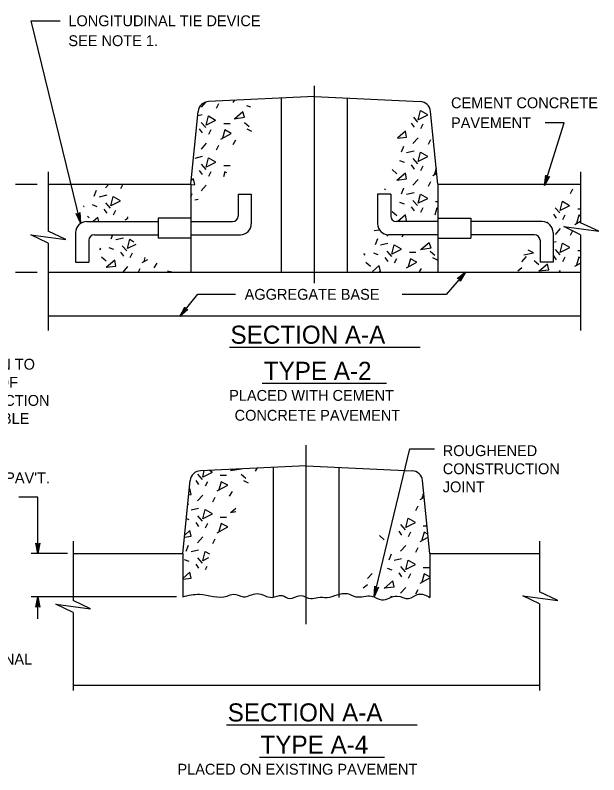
# Model space of a CAD drawing. Extents: x -49.1 to -41.9, y 44.5 to 54.6.
# Drawn here: x -45.264 to -42.042, y 50.267 to 54.464 of the extents above; entities that cross this region are included whole.
import ezdxf

# ---------------------------------------------------------------- set-up
doc = ezdxf.new("R2010")
doc.units = 0
for name, color, linetype in [('DETL-DIMS', 7, 'Continuous'), ('DETL-LINE', 7, 'Continuous'), ('DETL-NOTE', 7, 'Continuous'), ('DETL-PATT', 7, 'Continuous'), ('DETL-TITL', 7, 'Continuous')]:
    doc.layers.add(name, color=color, linetype=linetype)

msp = doc.modelspace()

# ---------------------------------------------------------------- linework, layer by layer
at = {"layer": 'DETL-DIMS'}
for p, q in [((-44.9035, 53.3158), (-45.1755, 54.4329)), ((-45.1755, 54.4329), (-45.0161, 54.4329)), ((-43.6122, 52.984), (-43.6122, 54.0742)), ((-42.3422, 53.5223), (-42.2343, 53.8696)), ((-42.2343, 53.8696), (-42.339, 53.8696)), ((-45.2621, 53.5295), (-45.1424, 53.5295)), ((-45.2621, 53.0446), (-45.1424, 53.0446)), ((-42.7789, 53.0446), (-42.8844, 52.9214)), ((-44.3546, 52.7995), (-44.2561, 52.9215)), ((-44.2561, 52.9215), (-44.0479, 52.9215)), ((-42.8844, 52.9214), (-43.1284, 52.9214)), ((-43.6569, 51.0992), (-43.6569, 52.088)), ((-43.2818, 51.2508), (-43.0853, 52.0677)), ((-43.0853, 52.0677), (-42.9492, 52.0677)), ((-45.1392, 51.8005), (-45.2438, 51.8005)), ((-45.1392, 51.4898), (-45.1392, 51.8005)), ((-44.9752, 51.4898), (-45.1762, 51.4898)), ((-44.3735, 51.2504), (-45.1762, 51.2504)), ((-45.1392, 51.1293), (-45.1392, 51.2504))]:
    msp.add_line(p, q, dxfattribs=at)
for points in [[(-42.3422, 53.5223), (-42.3355, 53.5794), (-42.334, 53.5743), (-42.331, 53.5711), (-42.3276, 53.5693), (-42.3238, 53.5688), (-42.3195, 53.5698), (-42.3153, 53.5731), (-42.3422, 53.5223), (-42.3195, 53.5698), (-42.3238, 53.5688), (-42.3422, 53.5223), (-42.3276, 53.5693), (-42.331, 53.5711), (-42.3422, 53.5223), (-42.334, 53.5743)], [(-42.3422, 53.5223), (-42.3355, 53.5794), (-42.334, 53.5743), (-42.331, 53.5711), (-42.3276, 53.5693), (-42.3238, 53.5688), (-42.3195, 53.5698), (-42.3153, 53.5731), (-42.3422, 53.5223), (-42.3195, 53.5698), (-42.3238, 53.5688), (-42.3422, 53.5223), (-42.3276, 53.5693), (-42.331, 53.5711), (-42.3422, 53.5223), (-42.334, 53.5743)], [(-44.9035, 53.3158), (-44.9271, 53.3681), (-44.9232, 53.3646), (-44.919, 53.3634), (-44.9151, 53.3636), (-44.9116, 53.3651), (-44.9085, 53.3682), (-44.9065, 53.3732), (-44.9035, 53.3158), (-44.9085, 53.3682), (-44.9116, 53.3651), (-44.9035, 53.3158), (-44.9151, 53.3636), (-44.919, 53.3634), (-44.9035, 53.3158), (-44.9232, 53.3646)], [(-44.9035, 53.3158), (-44.9271, 53.3681), (-44.9232, 53.3646), (-44.919, 53.3634), (-44.9151, 53.3636), (-44.9116, 53.3651), (-44.9085, 53.3682), (-44.9065, 53.3732), (-44.9035, 53.3158), (-44.9085, 53.3682), (-44.9116, 53.3651), (-44.9035, 53.3158), (-44.9151, 53.3636), (-44.919, 53.3634), (-44.9035, 53.3158), (-44.9232, 53.3646)], [(-42.7789, 53.0446), (-42.8076, 52.9948), (-42.807, 53.0001), (-42.8085, 53.0042), (-42.8109, 53.0072), (-42.8142, 53.0092), (-42.8185, 53.0099), (-42.8237, 53.0086), (-42.7789, 53.0446), (-42.8185, 53.0099), (-42.8142, 53.0092), (-42.7789, 53.0446), (-42.8109, 53.0072), (-42.8085, 53.0042), (-42.7789, 53.0446), (-42.807, 53.0001)], [(-44.3546, 52.7995), (-44.3274, 52.8501), (-44.3278, 52.8448), (-44.3262, 52.8407), (-44.3237, 52.8378), (-44.3203, 52.8359), (-44.316, 52.8353), (-44.3109, 52.8368), (-44.3546, 52.7995), (-44.316, 52.8353), (-44.3203, 52.8359), (-44.3546, 52.7995), (-44.3237, 52.8378), (-44.3262, 52.8407), (-44.3546, 52.7995), (-44.3278, 52.8448)], [(-45.1392, 51.4898), (-45.1498, 51.5463), (-45.1468, 51.5419), (-45.143, 51.5397), (-45.1392, 51.539), (-45.1354, 51.5397), (-45.1317, 51.5419), (-45.1286, 51.5463), (-45.1392, 51.4898), (-45.1317, 51.5419), (-45.1354, 51.5397), (-45.1392, 51.4898), (-45.1392, 51.539), (-45.143, 51.5397), (-45.1392, 51.4898), (-45.1468, 51.5419)], [(-43.2818, 51.2508), (-43.2789, 51.3082), (-43.277, 51.3033), (-43.2739, 51.3002), (-43.2703, 51.2987), (-43.2665, 51.2984), (-43.2623, 51.2997), (-43.2583, 51.3033), (-43.2818, 51.2508), (-43.2623, 51.2997), (-43.2665, 51.2984), (-43.2818, 51.2508), (-43.2703, 51.2987), (-43.2739, 51.3002), (-43.2818, 51.2508), (-43.277, 51.3033)], [(-45.1392, 51.2504), (-45.1286, 51.1939), (-45.1317, 51.1982), (-45.1354, 51.2005), (-45.1392, 51.2011), (-45.143, 51.2005), (-45.1468, 51.1982), (-45.1498, 51.1939), (-45.1392, 51.2504), (-45.1468, 51.1982), (-45.143, 51.2005), (-45.1392, 51.2504), (-45.1392, 51.2011), (-45.1354, 51.2005), (-45.1392, 51.2504), (-45.1317, 51.1982)]]:
    msp.add_lwpolyline(points, dxfattribs=at)
at = {"layer": 'DETL-LINE'}
for p, q in [((-43.6122, 54.0143), (-44.1962, 53.9865)), ((-43.6122, 54.0143), (-43.0281, 53.9865)), ((-43.794, 53.0446), (-43.794, 54.0033)), ((-43.4304, 53.0446), (-43.4304, 54.0033)), ((-44.2939, 53.5295), (-44.2537, 53.932)), ((-42.9305, 53.5295), (-42.9707, 53.932)), ((-45.0818, 53.5978), (-45.0818, 53.2701)), ((-42.1426, 53.5978), (-42.1426, 53.3173)), ((-45.0818, 53.5295), (-44.2939, 53.5295)), ((-44.2939, 53.5295), (-44.2939, 53.4082)), ((-44.2939, 53.5295), (-44.2939, 53.0446)), ((-42.9305, 53.5295), (-42.1426, 53.5295)), ((-42.9305, 53.5295), (-42.9305, 53.4082)), ((-42.9305, 53.5295), (-42.9305, 53.0446)), ((-44.0333, 53.4749), (-44.0333, 53.3537)), ((-44.0333, 53.4749), (-43.9606, 53.4749)), ((-43.9606, 53.4749), (-43.9606, 53.3113)), ((-43.2638, 53.4749), (-43.2638, 53.3113)), ((-43.1911, 53.4749), (-43.2638, 53.4749)), ((-43.1911, 53.4749), (-43.1911, 53.3537)), ((-44.2939, 53.3598), (-44.2939, 53.2143)), ((-44.2939, 53.3598), (-44.2939, 53.2143)), ((-42.9305, 53.3598), (-42.9305, 53.2143)), ((-42.9305, 53.3598), (-42.9305, 53.2143)), ((-44.8697, 53.3234), (-44.4757, 53.3234)), ((-44.2939, 53.3416), (-44.4757, 53.3416)), ((-44.4757, 53.3416), (-44.4757, 53.2325)), ((-44.2939, 53.3234), (-44.0636, 53.3234)), ((-42.9305, 53.3234), (-43.1608, 53.3234)), ((-42.9305, 53.3416), (-42.7486, 53.3416)), ((-42.7486, 53.3416), (-42.7486, 53.2325)), ((-42.3547, 53.3234), (-42.7486, 53.3234)), ((-44.9303, 53.2628), (-44.9303, 53.0992)), ((-42.2941, 53.2628), (-42.2941, 53.0992)), ((-44.8575, 53.2204), (-44.8575, 53.0992)), ((-44.8272, 53.2507), (-44.4757, 53.2507)), ((-44.2939, 53.2325), (-44.4757, 53.2325)), ((-44.2939, 53.2507), (-44.0212, 53.2507)), ((-42.9305, 53.2507), (-43.2032, 53.2507)), ((-42.9305, 53.2325), (-42.7486, 53.2325)), ((-42.3971, 53.2507), (-42.7486, 53.2507)), ((-42.3668, 53.2204), (-42.3668, 53.0992)), ((-42.1426, 53.2508), (-42.1426, 52.7225)), ((-45.0818, 53.2035), (-45.0818, 52.7225)), ((-44.9303, 53.0992), (-44.8575, 53.0992)), ((-42.2941, 53.0992), (-42.3668, 53.0992)), ((-45.0818, 53.0446), (-42.1426, 53.0446)), ((-45.0818, 52.8022), (-42.1426, 52.8022)), ((-43.6569, 51.9746), (-44.241, 51.9468)), ((-43.8387, 51.2474), (-43.8387, 51.9636)), ((-43.6569, 51.9746), (-43.0729, 51.9468)), ((-43.4751, 51.2474), (-43.4751, 51.9636)), ((-44.3386, 51.4898), (-44.2984, 51.8923)), ((-42.9752, 51.4898), (-43.0154, 51.8923)), ((-44.9447, 51.5581), (-44.9447, 51.2305)), ((-42.3691, 51.5581), (-42.3691, 51.2777)), ((-44.9447, 51.4898), (-44.3386, 51.4898)), ((-44.3386, 51.4898), (-44.3386, 51.2504)), ((-42.9752, 51.4898), (-42.3691, 51.4898)), ((-42.9752, 51.4898), (-42.9752, 51.2474)), ((-42.3691, 51.2111), (-42.3691, 50.7326)), ((-44.9447, 51.1639), (-44.9447, 50.7326)), ((-44.9447, 50.7625), (-42.3691, 50.7625))]:
    msp.add_line(p, q, dxfattribs=at)
for points in [[(-42.1426, 53.2508), (-42.2345, 53.2957), (-42.0422, 53.2696), (-42.1426, 53.3173)], [(-45.0818, 53.2035), (-45.1769, 53.2501), (-44.9847, 53.224), (-45.0818, 53.2701)], [(-42.3691, 51.2111), (-42.461, 51.2561), (-42.2688, 51.2299), (-42.3691, 51.2777)], [(-44.9447, 51.1639), (-45.0398, 51.2104), (-44.8476, 51.1843), (-44.9447, 51.2305)]]:
    msp.add_lwpolyline(points, dxfattribs=at)
for centre, radius, start, end in [((-44.1934, 53.926), 0.0606, 92.7268, 174.2895), ((-43.031, 53.926), 0.0606, 5.7105, 87.2732), ((-44.0636, 53.3537), 0.0303, 270, 0), ((-43.1608, 53.3537), 0.0303, 180, 270), ((-44.8697, 53.2628), 0.0606, 90, 180), ((-44.0212, 53.3113), 0.0606, 270, 0), ((-43.2032, 53.3113), 0.0606, 180, 270), ((-42.3547, 53.2628), 0.0606, 0, 90), ((-44.8272, 53.2204), 0.0303, 90, 180), ((-42.3971, 53.2204), 0.0303, 0, 90), ((-44.2381, 51.8863), 0.0606, 92.7268, 174.2895), ((-43.0758, 51.8863), 0.0606, 5.7105, 87.2732)]:
    msp.add_arc(centre, radius, start, end, dxfattribs=at)
msp.add_spline([(-44.3386, 51.2504), (-44.2465, 51.2646), (-44.0945, 51.2542), (-44.06, 51.2646), (-44.0047, 51.2507), (-43.9287, 51.268), (-43.8458, 51.2473), (-43.7906, 51.2576), (-43.7491, 51.2404), (-43.6904, 51.2576), (-43.6317, 51.2404), (-43.5937, 51.2473), (-43.5419, 51.2473), (-43.4314, 51.268), (-43.383, 51.2507), (-43.2967, 51.2542), (-43.2414, 51.2335), (-43.1551, 51.2542), (-43.0929, 51.2404), (-43.0377, 51.2646), (-42.9752, 51.2474)], degree=3, dxfattribs=at)
at = {"layer": 'DETL-PATT'}
for p, q in [((-44.213, 53.9829), (-44.238, 53.9551)), ((-44.1418, 53.9743), (-44.1546, 53.9486)), ((-44.0615, 53.9808), (-44.0538, 53.9931)), ((-43.9877, 53.9647), (-43.9652, 53.9583)), ((-44.2316, 53.9134), (-44.2561, 53.9077)), ((-43.0658, 53.8998), (-43.0426, 53.8736)), ((-44.238, 53.8716), (-44.2124, 53.8427)), ((-44.1129, 53.8652), (-44.0776, 53.8652)), ((-43.9974, 53.8716), (-43.9717, 53.8492)), ((-43.0779, 53.8672), (-43.0618, 53.8448)), ((-43.0137, 53.8608), (-43.0265, 53.8351)), ((-44.2477, 53.8363), (-44.2316, 53.8139)), ((-44.1835, 53.8299), (-44.1963, 53.8042)), ((-43.9845, 53.8363), (-43.9588, 53.8235)), ((-44.0615, 53.7497), (-44.0455, 53.7754)), ((-43.0394, 53.787), (-43.0682, 53.7549)), ((-42.972, 53.7742), (-42.9848, 53.7485)), ((-44.2091, 53.7561), (-44.238, 53.724)), ((-44.1418, 53.7433), (-44.1546, 53.7176)), ((-43.1196, 53.7389), (-43.1324, 53.7068)), ((-44.2316, 53.6823), (-44.2733, 53.6727)), ((-43.0618, 53.7132), (-43.1035, 53.7036)), ((-44.238, 53.6406), (-44.2124, 53.6117)), ((-43.142, 53.6618), (-43.1164, 53.6522)), ((-43.0779, 53.6362), (-43.0618, 53.6137)), ((-43.0682, 53.6715), (-43.0426, 53.6426)), ((-44.2477, 53.6053), (-44.2316, 53.5828)), ((-44.1835, 53.5989), (-44.1963, 53.5732)), ((-44.1129, 53.6341), (-44.0776, 53.6341)), ((-43.1837, 53.6105), (-43.1581, 53.588)), ((-43.0137, 53.6298), (-43.0265, 53.6041)), ((-43.0394, 53.5559), (-43.0682, 53.5239)), ((-44.748, 53.5296), (-44.7654, 53.5103)), ((-44.6691, 53.5296), (-44.6819, 53.5039)), ((-44.2091, 53.525), (-44.238, 53.4929)), ((-42.972, 53.5431), (-42.9848, 53.5174)), ((-44.8167, 53.4943), (-44.8295, 53.4622)), ((-44.7589, 53.4686), (-44.8006, 53.459)), ((-44.2894, 53.4769), (-44.2959, 53.4607)), ((-43.2246, 53.5041), (-43.2191, 53.5014)), ((-43.1196, 53.5078), (-43.1324, 53.4757)), ((-43.0618, 53.4821), (-43.1035, 53.4725)), ((-42.1873, 53.503), (-42.2001, 53.4773)), ((-44.7654, 53.4269), (-44.7397, 53.398)), ((-44.2959, 53.4607), (-44.2959, 53.4607)), ((-44.2959, 53.4607), (-44.2959, 53.4607)), ((-44.2959, 53.4607), (-44.2959, 53.4607)), ((-44.2542, 53.446), (-44.2733, 53.4416)), ((-43.142, 53.4308), (-43.1164, 53.4211)), ((-43.0682, 53.4404), (-43.0426, 53.4115)), ((-42.9431, 53.434), (-42.9337, 53.434)), ((-44.8392, 53.4172), (-44.8135, 53.4076)), ((-44.775, 53.3916), (-44.7589, 53.3691)), ((-44.7108, 53.3851), (-44.7236, 53.3595)), ((-43.0779, 53.4051), (-43.0618, 53.3826)), ((-43.0137, 53.3987), (-43.0265, 53.373)), ((-42.2836, 53.4003), (-42.2579, 53.3714)), ((-42.1584, 53.3939), (-42.1426, 53.3939)), ((-44.8657, 53.3526), (-44.8552, 53.3434)), ((-43.1837, 53.3794), (-43.1581, 53.357)), ((-42.2932, 53.365), (-42.2771, 53.3426)), ((-42.229, 53.3586), (-42.2418, 53.3329)), ((-42.2547, 53.2848), (-42.2836, 53.2527)), ((-42.1873, 53.272), (-42.2001, 53.2463)), ((-44.7272, 53.2498), (-44.7369, 53.2254)), ((-44.6663, 53.2318), (-44.7081, 53.2222)), ((-43.2644, 53.2276), (-43.2772, 53.1955)), ((-43.2066, 53.2508), (-43.213, 53.2436)), ((-43.1229, 53.2507), (-43.1296, 53.2372)), ((-44.7466, 53.1805), (-44.7209, 53.1709)), ((-44.6728, 53.1901), (-44.6471, 53.1612)), ((-43.2066, 53.2019), (-43.2483, 53.1923)), ((-42.2771, 53.211), (-42.2941, 53.2071)), ((-44.6824, 53.1548), (-44.6663, 53.1324)), ((-44.6182, 53.1484), (-44.631, 53.1227)), ((-43.2868, 53.1506), (-43.2612, 53.1409)), ((-43.213, 53.1602), (-43.1874, 53.1313)), ((-43.0879, 53.1538), (-43.0526, 53.1538)), ((-42.9723, 53.1602), (-42.9467, 53.1377)), ((-42.2932, 53.134), (-42.2771, 53.1115)), ((-42.2836, 53.1692), (-42.2579, 53.1404)), ((-42.1584, 53.1628), (-42.1426, 53.1628)), ((-44.7883, 53.1291), (-44.7626, 53.1067)), ((-44.4962, 53.0682), (-44.4802, 53.0938)), ((-43.3286, 53.0992), (-43.3029, 53.0767)), ((-43.2226, 53.1249), (-43.2066, 53.1024)), ((-43.1585, 53.1185), (-43.1713, 53.0928)), ((-42.9595, 53.1249), (-42.9338, 53.112)), ((-42.4665, 53.1019), (-42.4408, 53.1307)), ((-42.3991, 53.1083), (-42.3734, 53.0858)), ((-42.229, 53.1275), (-42.2418, 53.1019)), ((-44.6439, 53.0746), (-44.6707, 53.0448)), ((-44.5765, 53.0617), (-44.585, 53.0448)), ((-44.4224, 53.0521), (-44.4, 53.0457)), ((-43.032, 53.0454), (-43.0205, 53.0639)), ((-42.4889, 53.0505), (-42.4665, 53.0698)), ((-42.2547, 53.0537), (-42.2629, 53.0446)), ((-43.937, 51.9441), (-43.9273, 51.9635)), ((-44.2579, 51.9281), (-44.2322, 51.8992)), ((-44.1327, 51.9217), (-44.0974, 51.9217)), ((-44.0172, 51.9281), (-43.9915, 51.9056)), ((-44.2675, 51.8928), (-44.2515, 51.8703)), ((-44.2033, 51.8864), (-44.2161, 51.8607)), ((-44.0044, 51.8928), (-43.9787, 51.88)), ((-44.0814, 51.8062), (-44.0653, 51.8318)), ((-44.229, 51.8126), (-44.2579, 51.7805)), ((-44.1616, 51.7997), (-44.1744, 51.7741)), ((-44.3092, 51.7644), (-44.3118, 51.7579)), ((-43.0407, 51.7519), (-43.0536, 51.7262)), ((-44.2515, 51.7388), (-44.2932, 51.7291)), ((-44.3193, 51.6828), (-44.306, 51.6778)), ((-44.2579, 51.697), (-44.2322, 51.6682)), ((-44.1327, 51.6906), (-44.0974, 51.6906)), ((-44.2675, 51.6617), (-44.2515, 51.6393)), ((-44.2033, 51.6553), (-44.2161, 51.6296)), ((-43.137, 51.6492), (-43.1113, 51.6203)), ((-43.0118, 51.6428), (-42.9912, 51.6428)), ((-44.229, 51.5815), (-44.2579, 51.5494)), ((-43.2525, 51.5882), (-43.2269, 51.5658)), ((-43.1466, 51.6139), (-43.1306, 51.5914)), ((-43.0824, 51.6075), (-43.0953, 51.5818)), ((-44.1616, 51.5687), (-44.1744, 51.543)), ((-44.3092, 51.5334), (-44.322, 51.5013)), ((-44.2515, 51.5077), (-44.2932, 51.4981)), ((-43.1081, 51.5336), (-43.137, 51.5016)), ((-43.0407, 51.5208), (-43.0536, 51.4951)), ((-44.3317, 51.4564), (-44.306, 51.4467)), ((-44.2579, 51.466), (-44.2322, 51.4371)), ((-43.1883, 51.4855), (-43.2012, 51.4534)), ((-43.1306, 51.4599), (-43.1723, 51.4502)), ((-44.2675, 51.4307), (-44.2515, 51.4082)), ((-44.207, 51.4169), (-44.2161, 51.3986)), ((-43.137, 51.4181), (-43.1113, 51.3892)), ((-43.0118, 51.4117), (-42.9765, 51.4117)), ((-43.3199, 51.3507), (-43.2942, 51.3796)), ((-43.2108, 51.4085), (-43.1851, 51.3989)), ((-43.1466, 51.3828), (-43.1306, 51.3604)), ((-43.0824, 51.3764), (-43.0953, 51.3507)), ((-43.3424, 51.2994), (-43.3199, 51.3186)), ((-43.1081, 51.3026), (-43.137, 51.2705)), ((-43.0407, 51.2897), (-43.0536, 51.2641)), ((-43.1883, 51.2545), (-43.1907, 51.2485))]:
    msp.add_line(p, q, dxfattribs=at)
for points in [[(-42.988, 53.9122), (-43.0394, 53.8865), (-43.0265, 53.9378), (-42.988, 53.9154)], [(-44.1578, 53.8813), (-44.2091, 53.8556), (-44.1963, 53.9069), (-44.1578, 53.8845)], [(-44.0551, 53.8909), (-43.9974, 53.9005), (-44.007, 53.9294), (-44.0519, 53.8909)], [(-44.1289, 53.7786), (-44.0712, 53.8106), (-44.1065, 53.8299), (-44.1193, 53.785)], [(-43.1534, 53.7843), (-43.1035, 53.7902), (-43.1099, 53.8223), (-43.1534, 53.7846)], [(-42.988, 53.6811), (-43.0394, 53.6554), (-43.0265, 53.7068), (-42.988, 53.6843)], [(-44.1578, 53.6502), (-44.2091, 53.6245), (-44.1963, 53.6759), (-44.1578, 53.6534)], [(-44.0966, 53.5935), (-44.1065, 53.5989), (-44.1146, 53.5703)], [(-42.9397, 53.6191), (-42.9495, 53.5848)], [(-44.294, 53.5258), (-44.2733, 53.5282), (-44.2797, 53.5603), (-44.2919, 53.5498)], [(-43.1581, 53.5527), (-43.1035, 53.5591), (-43.1099, 53.5912), (-43.1581, 53.5495)], [(-42.9591, 53.5784), (-42.9368, 53.5908)], [(-42.988, 53.45), (-43.0394, 53.4244), (-43.0265, 53.4757), (-42.988, 53.4532)], [(-44.6851, 53.4365), (-44.7365, 53.4108), (-44.7236, 53.4622), (-44.6851, 53.4397)], [(-42.2033, 53.4099), (-42.2547, 53.3843), (-42.2418, 53.4356), (-42.2033, 53.4131)], [(-44.8858, 53.4073), (-44.8841, 53.4076), (-44.8864, 53.4087)], [(-43.1911, 53.4204), (-43.187, 53.4211), (-43.1911, 53.4232)], [(-42.9351, 53.3979), (-42.9366, 53.3987), (-42.9478, 53.3598)], [(-44.8025, 53.324), (-44.8071, 53.3466), (-44.8329, 53.3242)], [(-44.6562, 53.3338), (-44.6399, 53.3429)], [(-44.6441, 53.349), (-44.6466, 53.3402)], [(-43.1426, 53.3235), (-43.1035, 53.3281), (-43.1099, 53.3602), (-43.1523, 53.3234)], [(-42.1426, 53.3535), (-42.152, 53.3586), (-42.1648, 53.3137)], [(-43.1426, 53.3235), (-43.1426, 53.3235)], [(-42.3244, 53.3159), (-42.3253, 53.3201), (-42.3275, 53.3182)], [(-42.1744, 53.3072), (-42.1426, 53.325)], [(-43.2816, 53.275), (-43.255, 53.2781)], [(-44.5979, 53.1971), (-44.6439, 53.1741), (-44.631, 53.2254), (-44.6086, 53.2123)], [(-43.1328, 53.1698), (-43.1841, 53.1441), (-43.1713, 53.1955), (-43.1328, 53.173)], [(-43.0261, 53.1684), (-42.9683, 53.178), (-42.9779, 53.2069), (-43.0228, 53.1684)], [(-42.2033, 53.1789), (-42.2547, 53.1532), (-42.2418, 53.2046), (-42.2033, 53.1821)], [(-44.7977, 53.1697), (-44.7915, 53.1709), (-44.7975, 53.1739)], [(-43.3379, 53.1398), (-43.3318, 53.1409), (-43.3396, 53.1449)], [(-42.4556, 53.1399), (-42.4023, 53.15), (-42.4327, 53.1652)], [(-44.7626, 53.0714), (-44.7081, 53.0778), (-44.7145, 53.1099), (-44.7618, 53.0689)], [(-44.5636, 53.097), (-44.532, 53.1146)], [(-44.5476, 53.1257), (-44.554, 53.1035)], [(-43.1039, 53.0671), (-43.0461, 53.0992), (-43.0815, 53.1185), (-43.0943, 53.0735)], [(-42.1744, 53.0762), (-42.1426, 53.0939)], [(-42.1426, 53.1224), (-42.152, 53.1275), (-42.1648, 53.0826)], [(-43.2546, 53.0471), (-43.2483, 53.0479), (-43.2548, 53.08), (-43.2923, 53.0474)], [(-42.3734, 53.0505), (-42.3189, 53.0569), (-42.3253, 53.089), (-42.3734, 53.0473)], [(-44.0749, 51.9474), (-44.0172, 51.957), (-44.0177, 51.9587)], [(-44.1776, 51.9377), (-44.229, 51.9121), (-44.22, 51.9479)], [(-44.1922, 51.9494), (-44.1776, 51.9409)], [(-44.0612, 51.9564), (-44.0717, 51.9474)], [(-44.1487, 51.835), (-44.091, 51.8671), (-44.1263, 51.8864), (-44.1391, 51.8415)], [(-44.3062, 51.8143), (-44.2932, 51.8158), (-44.2996, 51.8479), (-44.3031, 51.8448)], [(-43.0279, 51.7872), (-43.0074, 51.7985)], [(-43.01, 51.8227), (-43.0183, 51.7936)], [(-43.01, 51.8227), (-43.01, 51.8227)], [(-43.01, 51.8227), (-43.01, 51.8227)], [(-44.1776, 51.7067), (-44.229, 51.681), (-44.2161, 51.7324), (-44.1776, 51.7099)], [(-44.0749, 51.7163), (-44.0452, 51.7212)], [(-44.0458, 51.7385), (-44.0717, 51.7163)], [(-43.0568, 51.6588), (-43.1081, 51.6331), (-43.0953, 51.6845), (-43.0568, 51.662)], [(-44.1487, 51.604), (-44.091, 51.6361), (-44.1263, 51.6553), (-44.1391, 51.6104)], [(-44.3296, 51.5804), (-44.2932, 51.5847), (-44.2996, 51.6168), (-44.3284, 51.5918)], [(-43.0279, 51.5561), (-42.9846, 51.5801)], [(-42.9864, 51.5971), (-43.0054, 51.6075), (-43.0183, 51.5625)], [(-44.1967, 51.4661), (-44.229, 51.4499), (-44.2161, 51.5013), (-44.1918, 51.4871)], [(-43.0568, 51.4277), (-43.1081, 51.4021), (-43.0953, 51.4534), (-43.0568, 51.431)], [(-44.3394, 51.3482), (-44.2932, 51.3537), (-44.2996, 51.3858), (-44.3393, 51.3513)], [(-42.9752, 51.3599), (-43.0054, 51.3764), (-43.0183, 51.3315)], [(-43.2269, 51.2994), (-43.1723, 51.3058), (-43.1787, 51.3379), (-43.2269, 51.2962)], [(-43.0279, 51.3251), (-42.9752, 51.3543)]]:
    msp.add_lwpolyline(points, dxfattribs=at)
at = {"layer": 'DETL-TITL'}
for p, q in [((-44.0818, 52.6299), (-43.0282, 52.6299)), ((-43.9001, 52.4302), (-43.2139, 52.4302)), ((-44.0979, 50.5429), (-43.0443, 50.5429)), ((-43.9162, 50.3648), (-43.226, 50.3648))]:
    msp.add_line(p, q, dxfattribs=at)

# ---------------------------------------------------------------- texts
at = {"layer": 'DETL-NOTE'}
for s, p in [('LONGITUDINAL TIE DEVICE', (-44.9706, 54.4028)), ('SEE NOTE 1.', (-44.9706, 54.2928)), ('CEMENT CONCRETE', (-42.858, 53.9496)), ('PAVEMENT', (-42.858, 53.8396)), ('AGGREGATE BASE', (-43.9975, 52.8915)), ('DEPTH OF GUTTER PAN TO', (-46.2337, 52.5054)), ('MATCH LAMINATIONS OF', (-46.2337, 52.4054)), ('PLACED WITH CEMENT', (-44.0828, 52.3331)), ('PROPOSED PAVING SECTION', (-46.2337, 52.3054)), ('AS CLOSELY AS POSSIBLE', (-46.2337, 52.2054)), ('CONCRETE PAVEMENT', (-44.0528, 52.2231)), ('ROUGHENED', (-42.9037, 52.0277)), ('CONSTRUCTION', (-42.9037, 51.9277)), ('4" (MIN.) EXISTING PAV\'T.', (-46.0568, 51.8779)), ('JOINT', (-42.9037, 51.8277)), ('BELOW FINAL', (-45.7099, 50.8755)), ('PLACED ON EXISTING PAVEMENT', (-44.3683, 50.2677))]:
    msp.add_text(s, height=0.06, dxfattribs=at).set_placement(p)
at = {"layer": 'DETL-TITL'}
for s, p in [('SECTION A-A', (-44.0754, 52.6485)), ('TYPE A-2', (-43.8916, 52.4488)), ('SECTION A-A', (-44.0909, 50.5615)), ('TYPE A-4', (-43.9097, 50.3834))]:
    msp.add_text(s, height=0.1, dxfattribs=at).set_placement(p)

doc.saveas('drawing.dxf')
